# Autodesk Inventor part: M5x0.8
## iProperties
IsCustomPart: 1
Created: 2009-02
Part Number: M5x0.8
Material: 강, 연강
Description: 6각 머리 볼트 및 6각 머리 나사
Document SubType Name: Modeling
Standard: KS B 1002
Designer: 한국산업디자인학원
Standards Organization: KS
Language: ko-KR
Size Designation: A  M 5 x 25
Categories: <MemberInstance><Categories><Category DisplayName="조임쇠" InternalName="e4da775c-781d-43d5-af7c-5136215cf5a6" Mnemonic="FSTN"><Category DisplayName="볼트" InternalN
Density: 1 g/cm^3
Author: 한국산업디자인학원
